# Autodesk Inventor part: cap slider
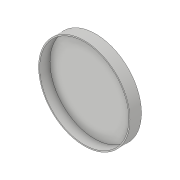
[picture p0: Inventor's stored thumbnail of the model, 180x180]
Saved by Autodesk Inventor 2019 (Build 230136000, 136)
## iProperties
Created: 2019-10
Part Number: cap slider
Material: Generic
Document SubType Name: Modeling
Designer: hp
Density: 1 g/cm^3
Appearance: Default
Author: hp
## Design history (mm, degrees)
sketch "Sketch1"
  geometry: L1 (0, 0)-(27.773, 28.786); L2 (0, 0)-(-28.786, 27.773); L3 (0, 0)-(-27.773, -28.786); L4 (0, 0)-(28.786, -27.773); L5 (0, 40)-(0, 0); L6 (0, -40)-(0, 0); A1 r 40 centre (0, 0) between (27.773, 28.786) and (-28.786, 27.773); 1 further point
  constraints: 12 end point, 6 point on circle, 1 centre point, 1 coincident, 1 collinear, 1 point on line, 1 vertical
  dimensions: "d0" = 80 diameter of A1
extrude "Extrusion1" new body sketch "Sketch1" distance "d1" = 10; taper "d2" = 0 deg
shell "Shell1" dims "d3" = 1
body "Solid1"
